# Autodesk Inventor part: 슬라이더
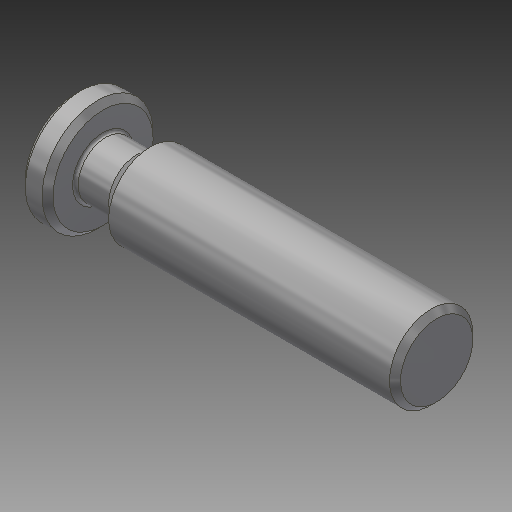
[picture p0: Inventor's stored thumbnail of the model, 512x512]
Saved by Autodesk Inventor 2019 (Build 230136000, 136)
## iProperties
Created: 2016-05
Part Number: 슬라이더
Document SubType Name: Modeling
Designer: mduedu
Density: 7.86 g/cm^3
Material: 강철, 연강
Appearance: 강철
Author: mduedu
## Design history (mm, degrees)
sketch "스케치1"
  geometry: L1 (-7.5, 0)-(57.5, 0); L2 (57.5, 0)-(57.5, 7.5); L3 (57.5, 7.5)-(0, 7.5); L4 (-7.5, 0)-(-7.5, 10); L5 (-7.5, 10)-(-2.5, 10); L6 (-2.5, 10)-(-2.5, 5); L7 (-2.5, 5)-(3.5, 5); L8 (3.5, 5)-(6, 7.5); A1 r 7.5 centre (0, 0) between (0, 7.5) and (-7.5, 0); 1 further point
  constraints: 16 end point, 3 perpendicular, 2 horizontal, 2 parallel, 2 point on circle, 2 point on line, 2 tangent, 1 centre point, 1 coincident
  dimensions: "d0" = 15 diameter of A1; "d1" = 65 distance of L1.start L1.end; "d19" = 20 diameter of L5 L1; "d20" = 10 diameter of L7 L1; "d21" = 5 distance of L4.end L5.end; "d22" = 135 deg angle of L8 L7; "d23" = 6 distance of L6.end L7.end
revolve "회전1" stored, may be unused: angle "d4" = 90 deg
chamfer "모따기2" distance "d24" = 1; stored, may be unused: second distance "d25" = 2, angle "d26" = 45 deg
fillet "모깎기1" dims "d27" = 0.5
node "솔리드1"
